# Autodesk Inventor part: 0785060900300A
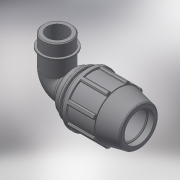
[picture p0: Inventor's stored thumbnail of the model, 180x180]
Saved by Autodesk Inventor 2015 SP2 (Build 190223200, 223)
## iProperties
Created: 2017-02
Part Number: 0785060900300A
Material: Generic
Description: PLASSON 90° ELBOW MALE ADAPTOR 90-3"
Document SubType Name: Modeling
Designer: KIM
Mass: 1366.09 g
Surface Area: 1816.46 cm^2
Volume: 1366.09 cm^3
Density: 1 g/cm^3
Appearance: Default
Author: KIM
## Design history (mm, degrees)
derived "87850.ipt"
feature "Solid1::87850.ipt"
tag "TaggingFeature1"
body "Solid1"
other parameters: "d4" = 19.41667, "d5" = 58.25, "d7" = 154, "d9" = 33.28571, "d11" = 7.76667, "d13" = 120 deg, "d14" = 108, "d15" = 12 deg, "d16" = 133.98, "d18" = 4.5, "d19" = 35 deg, "d20" = 17.5 deg, "d21" = 143.22, "d23" = 0, "d25" = 360 deg, "d27" = 3.08, "d33" = 1.8, "d42" = 86.21, "d43" = 4.62, "d46" = 2.7, "d51" = 233, "d68" = 15.53333, "d73" = 87.884, "d74" = 35, "d75" = 101.0666, "d76" = 61.5188, "d77" = 38.5, "d79" = 35.1536, "d80" = 2.63652, "d83" = 0, "d84" = 0, "d91" = 115.5, "d93" = 165, "d94" = 87.884, "d95" = 61.5188, "d96" = 15.53333, "d97" = 50 deg, "d98" = 3.88333, "d99" = 129.9606, "d100" = 3.88333, "d101" = 3.88333, "d102" = 10.26667, "d103" = 0, "E_" = 154, "A_" = 233, "l_" = 165, "l_2" = 35, "G_" = 87.884
